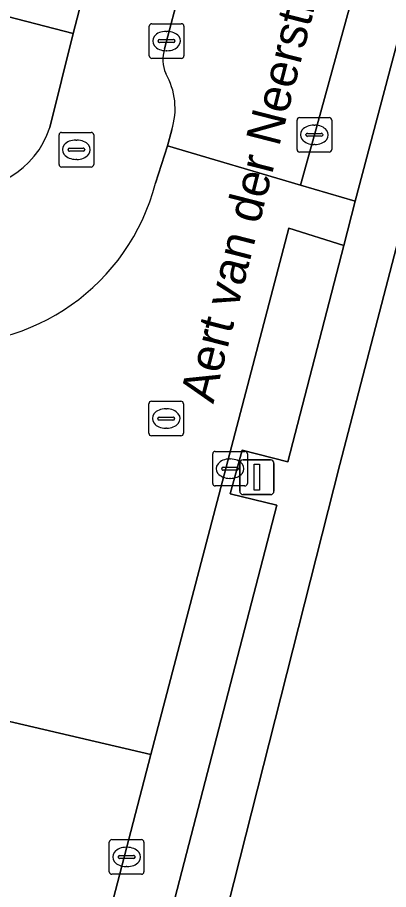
# Model space of a CAD drawing. Extents: x 163683 to 164494, y 382709 to 383872.
# Drawn here: x 164180.78 to 164191.5, y 383122.29 to 383147.46 of the extents above; entities that cross this region are included whole.
import ezdxf

# ---------------------------------------------------------------- set-up
doc = ezdxf.new("R2010")
doc.units = 0
for name, color, linetype in [('IMGEO_Brandkraan', 7, 'Continuous'), ('IMGEO_Erf', 7, 'Continuous'), ('IMGEO_Kolk', 7, 'Continuous'), ('IMGEO_Lichtmast', 7, 'Continuous'), ('IMGEO_Openbare_ruimte_label', 7, 'Continuous'), ('IMGEO_Pand', 7, 'Continuous'), ('IMGEO_Parkeervlak_open', 7, 'Continuous'), ('IMGEO_Rijbaan_lokaal_open', 7, 'Continuous'), ('IMGEO_Rioolput', 7, 'Continuous'), ('IMGEO_Voetpad_open', 7, 'Continuous')]:
    doc.layers.add(name, color=color, linetype=linetype)

msp = doc.modelspace()

# ---------------------------------------------------------------- linework, layer by layer
at = {"layer": 'IMGEO_Brandkraan'}
for p, q in [((164181.984, 383143.218), (164181.984, 383144.07)), ((164182.059, 383144.144), (164182.911, 383144.144)), ((164182.985, 383144.07), (164182.985, 383143.218)), ((164182.472, 383143.924), (164182.497, 383143.924)), ((164182.243, 383143.638), (164182.243, 383143.65)), ((164182.681, 383143.601), (164182.283, 383143.601)), ((164182.286, 383143.687), (164182.684, 383143.687)), ((164182.727, 383143.65), (164182.727, 383143.638)), ((164182.495, 383143.364), (164182.47, 383143.364)), ((164182.911, 383143.144), (164182.059, 383143.144))]:
    msp.add_line(p, q, dxfattribs=at)
for points in [[(164181.984, 383143.218), (164181.984, 383144.07)], [(164182.059, 383144.144), (164182.911, 383144.144)], [(164182.985, 383144.07), (164182.985, 383143.218)], [(164182.911, 383143.144), (164182.059, 383143.144)]]:
    msp.add_lwpolyline(points, dxfattribs=at)
for centre, radius, start, end in [((164182.061, 383144.068), 0.0765, 91.552, 178.448), ((164182.061, 383144.068), 0.0765, 91.552, 178.448), ((164182.909, 383144.068), 0.0765, 1.552, 88.448), ((164182.909, 383144.068), 0.0765, 1.552, 88.448), ((164182.283, 383143.647), 0.0403, 85.8775, 175.7526), ((164182.28, 383143.637), 0.0366, 178.938, 274.7102), ((164182.684, 383143.644), 0.043, 264.8664, 352.4533), ((164182.688, 383143.649), 0.0386, 1.7309, 96.639), ((164182.061, 383143.22), 0.0765, 181.552, 268.448), ((164182.061, 383143.22), 0.0765, 181.552, 268.448), ((164182.909, 383143.22), 0.0765, 271.552, 358.448), ((164182.909, 383143.22), 0.0765, 271.552, 358.448)]:
    msp.add_arc(centre, radius, start, end, dxfattribs=at)
for centre, major_axis, ratio, start_param, end_param in [((164182.471, 383143.644), (-0.387, 0.002), 0.722429, 4.712389, 7.853982), ((164182.496, 383143.644), (-0.39, 0.002), 0.717154, 1.570796, 4.712389)]:
    msp.add_ellipse(centre, major_axis=major_axis, ratio=ratio, start_param=start_param, end_param=end_param, dxfattribs=at)
at = {"layer": 'IMGEO_Erf'}
for points in [[(164181.718, 383144.288), (164182.395, 383147.001), (164175.872, 383148.696), (164176.511, 383151.151), (164171.876, 383152.355), (164172.911, 383156.337), (164174.58, 383155.903), (164175.305, 383158.691), (164174.256, 383158.963), (164174.916, 383161.499), (164174.956, 383161.653), (164175.727, 383164.619), (164176.798, 383164.341), (164177.507, 383167.068), (164178.03, 383169.079), (164177.044, 383169.336), (164177.995, 383172.992)], [(164235.416, 383087.174), (164249.772, 383143.475), (164225.172, 383149.691), (164224.38, 383146.62), (164220.869, 383147.526), (164218.278, 383138.676), (164221.781, 383137.775), (164221.055, 383134.95), (164220.387, 383132.353), (164217.268, 383133.155), (164217.081, 383132.425), (164215.494, 383132.833), (164216.241, 383135.98), (164212.881, 383136.834), (164213.61, 383139.702), (164214.266, 383142.284), (164217.626, 383141.431), (164219.349, 383147.981), (164215.956, 383148.856), (164216.694, 383151.712), (164199.271, 383156.404), (164196.004, 383157.255), (164190.094, 383134.558), (164181.769, 383101.734)]]:
    msp.add_lwpolyline(points, dxfattribs=at)
msp.add_arc((164179.316, 383145.046), 2.518, 257.4677, 342.4732, dxfattribs=at)
at = {"layer": 'IMGEO_Kolk'}
for p, q in [((164184.663, 383147.281), (164185.515, 383147.281)), ((164184.588, 383146.355), (164184.588, 383147.207)), ((164185.076, 383147.061), (164185.101, 383147.061)), ((164185.589, 383147.207), (164185.589, 383146.355)), ((164184.847, 383146.775), (164184.847, 383146.787)), ((164185.285, 383146.738), (164184.887, 383146.738)), ((164184.89, 383146.824), (164185.288, 383146.824)), ((164185.331, 383146.787), (164185.331, 383146.775)), ((164185.099, 383146.501), (164185.074, 383146.501)), ((164185.515, 383146.281), (164184.663, 383146.281)), ((164188.856, 383143.648), (164188.856, 383144.5)), ((164188.931, 383144.574), (164189.783, 383144.574)), ((164189.857, 383144.5), (164189.857, 383143.648)), ((164189.344, 383144.354), (164189.369, 383144.354)), ((164189.115, 383144.068), (164189.115, 383144.08)), ((164189.553, 383144.031), (164189.155, 383144.031)), ((164189.158, 383144.117), (164189.556, 383144.117)), ((164189.599, 383144.08), (164189.599, 383144.068)), ((164189.367, 383143.794), (164189.342, 383143.794)), ((164189.783, 383143.574), (164188.931, 383143.574)), ((164186.497, 383134.937), (164187.349, 383134.937)), ((164186.422, 383134.011), (164186.422, 383134.863)), ((164186.91, 383134.717), (164186.935, 383134.717)), ((164187.423, 383134.863), (164187.423, 383134.011)), ((164186.681, 383134.431), (164186.681, 383134.443)), ((164187.119, 383134.394), (164186.721, 383134.394)), ((164186.724, 383134.48), (164187.122, 383134.48)), ((164187.165, 383134.443), (164187.165, 383134.431)), ((164186.933, 383134.157), (164186.908, 383134.157)), ((164187.349, 383133.937), (164186.497, 383133.937)), ((164183.435, 383122.803), (164183.435, 383123.655)), ((164183.51, 383123.729), (164184.362, 383123.729)), ((164184.436, 383123.655), (164184.436, 383122.803)), ((164183.923, 383123.509), (164183.948, 383123.509)), ((164183.694, 383123.223), (164183.694, 383123.235)), ((164184.132, 383123.186), (164183.734, 383123.186)), ((164183.737, 383123.272), (164184.135, 383123.272)), ((164184.178, 383123.235), (164184.178, 383123.223)), ((164183.946, 383122.949), (164183.921, 383122.949)), ((164184.362, 383122.729), (164183.51, 383122.729))]:
    msp.add_line(p, q, dxfattribs=at)
for points in [[(164184.663, 383147.281), (164185.515, 383147.281)], [(164184.588, 383146.355), (164184.588, 383147.207)], [(164185.589, 383147.207), (164185.589, 383146.355)], [(164185.515, 383146.281), (164184.663, 383146.281)], [(164188.856, 383143.648), (164188.856, 383144.5)], [(164188.931, 383144.574), (164189.783, 383144.574)], [(164189.857, 383144.5), (164189.857, 383143.648)], [(164189.783, 383143.574), (164188.931, 383143.574)], [(164186.497, 383134.937), (164187.349, 383134.937)], [(164186.422, 383134.011), (164186.422, 383134.863)], [(164187.423, 383134.863), (164187.423, 383134.011)], [(164187.349, 383133.937), (164186.497, 383133.937)], [(164183.435, 383122.803), (164183.435, 383123.655)], [(164183.51, 383123.729), (164184.362, 383123.729)], [(164184.436, 383123.655), (164184.436, 383122.803)], [(164184.362, 383122.729), (164183.51, 383122.729)]]:
    msp.add_lwpolyline(points, dxfattribs=at)
for centre, radius, start, end in [((164184.665, 383147.205), 0.0765, 91.552, 178.448), ((164184.665, 383147.205), 0.0765, 91.552, 178.448), ((164185.513, 383147.205), 0.0765, 1.552, 88.448), ((164185.513, 383147.205), 0.0765, 1.552, 88.448), ((164184.887, 383146.784), 0.0403, 85.8775, 175.7526), ((164184.884, 383146.774), 0.0366, 178.938, 274.7102), ((164185.288, 383146.781), 0.043, 264.8664, 352.4533), ((164185.292, 383146.786), 0.0386, 1.7309, 96.639), ((164184.665, 383146.357), 0.0765, 181.552, 268.448), ((164184.665, 383146.357), 0.0765, 181.552, 268.448), ((164185.513, 383146.357), 0.0765, 271.552, 358.448), ((164185.513, 383146.357), 0.0765, 271.552, 358.448), ((164188.933, 383144.498), 0.0765, 91.552, 178.448), ((164188.933, 383144.498), 0.0765, 91.552, 178.448), ((164189.781, 383144.498), 0.0765, 1.552, 88.448), ((164189.781, 383144.498), 0.0765, 1.552, 88.448), ((164189.155, 383144.077), 0.0403, 85.8775, 175.7526), ((164189.152, 383144.067), 0.0366, 178.938, 274.7102), ((164189.556, 383144.074), 0.043, 264.8664, 352.4533), ((164189.56, 383144.079), 0.0386, 1.7309, 96.639), ((164188.933, 383143.65), 0.0765, 181.552, 268.448), ((164188.933, 383143.65), 0.0765, 181.552, 268.448), ((164189.781, 383143.65), 0.0765, 271.552, 358.448), ((164189.781, 383143.65), 0.0765, 271.552, 358.448), ((164186.499, 383134.861), 0.0765, 91.552, 178.448), ((164186.499, 383134.861), 0.0765, 91.552, 178.448), ((164187.347, 383134.861), 0.0765, 1.552, 88.448), ((164187.347, 383134.861), 0.0765, 1.552, 88.448), ((164186.721, 383134.44), 0.0403, 85.8775, 175.7526), ((164186.718, 383134.43), 0.0366, 178.938, 274.7102), ((164187.122, 383134.437), 0.043, 264.8664, 352.4533), ((164187.126, 383134.442), 0.0386, 1.7309, 96.639), ((164186.499, 383134.013), 0.0765, 181.552, 268.448), ((164186.499, 383134.013), 0.0765, 181.552, 268.448), ((164187.347, 383134.013), 0.0765, 271.552, 358.448), ((164187.347, 383134.013), 0.0765, 271.552, 358.448), ((164183.512, 383123.653), 0.0765, 91.552, 178.448), ((164183.512, 383123.653), 0.0765, 91.552, 178.448), ((164184.36, 383123.653), 0.0765, 1.552, 88.448), ((164184.36, 383123.653), 0.0765, 1.552, 88.448), ((164183.734, 383123.232), 0.0403, 85.8775, 175.7526), ((164183.731, 383123.222), 0.0366, 178.938, 274.7102), ((164184.135, 383123.229), 0.043, 264.8664, 352.4533), ((164184.139, 383123.234), 0.0386, 1.7309, 96.639), ((164183.512, 383122.805), 0.0765, 181.552, 268.448), ((164183.512, 383122.805), 0.0765, 181.552, 268.448), ((164184.36, 383122.805), 0.0765, 271.552, 358.448), ((164184.36, 383122.805), 0.0765, 271.552, 358.448)]:
    msp.add_arc(centre, radius, start, end, dxfattribs=at)
for centre, major_axis, ratio, start_param, end_param in [((164185.075, 383146.781), (-0.387, 0.002), 0.722429, 4.712389, 7.853982), ((164185.1, 383146.781), (-0.39, 0.002), 0.717154, 1.570796, 4.712389), ((164189.343, 383144.074), (-0.387, 0.002), 0.722429, 4.712389, 7.853982), ((164189.368, 383144.074), (-0.39, 0.002), 0.717154, 1.570796, 4.712389), ((164186.909, 383134.437), (-0.387, 0.002), 0.722429, 4.712389, 7.853982), ((164186.934, 383134.437), (-0.39, 0.002), 0.717154, 1.570796, 4.712389), ((164183.922, 383123.229), (-0.387, 0.002), 0.722429, 4.712389, 7.853982), ((164183.947, 383123.229), (-0.39, 0.002), 0.717154, 1.570796, 4.712389)]:
    msp.add_ellipse(centre, major_axis=major_axis, ratio=ratio, start_param=start_param, end_param=end_param, dxfattribs=at)
at = {"layer": 'IMGEO_Lichtmast'}
for p, q in [((164187.3, 383134.688), (164188.09, 383134.688)), ((164188.09, 383134.688), (164187.3, 383134.688)), ((164187.2, 383133.788), (164187.2, 383134.588)), ((164187.2, 383134.588), (164187.2, 383133.788)), ((164188.19, 383134.588), (164188.19, 383133.788)), ((164188.19, 383133.788), (164188.19, 383134.588)), ((164188.09, 383133.688), (164187.3, 383133.688)), ((164187.3, 383133.688), (164188.09, 383133.688))]:
    msp.add_line(p, q, dxfattribs=at)
msp.add_lwpolyline([(164187.62, 383134.563), (164187.77, 383134.563), (164187.77, 383133.813), (164187.62, 383133.813), (164187.62, 383134.563)], dxfattribs=at)
for centre, start, end in [((164187.3, 383134.588), 90, 180), ((164187.3, 383134.588), 90, 180), ((164188.09, 383134.588), 0, 90), ((164188.09, 383134.588), 360, 90), ((164187.3, 383133.788), 180, 270), ((164187.3, 383133.788), 180, 270), ((164188.09, 383133.788), 270, 0), ((164188.09, 383133.788), 270, 0)]:
    msp.add_arc(centre, 0.1, start, end, dxfattribs=at)
at = {"layer": 'IMGEO_Pand'}
msp.add_lwpolyline([(164184.067, 383153.438), (164174.58, 383155.903), (164172.911, 383156.337), (164171.876, 383152.355), (164176.511, 383151.151), (164175.872, 383148.696), (164182.395, 383147.001)], close=True, dxfattribs=at)
at = {"layer": 'IMGEO_Parkeervlak_open'}
for points in [[(164193.665, 383159.724), (164189.357, 383144.074), (164188.959, 383142.625), (164190.534, 383142.159), (164191.595, 383146.154), (164194.849, 383158.324)], [(164181.165, 383106.231), (164182.993, 383113.017), (164188.276, 383133.387), (164186.93, 383133.713), (164187.272, 383134.967), (164188.588, 383134.63), (164190.203, 383140.877), (164188.616, 383141.38), (164184.638, 383126.187), (164178.941, 383104.293)]]:
    msp.add_lwpolyline(points, dxfattribs=at)
at = {"layer": 'IMGEO_Rijbaan_lokaal_open'}
for points in [[(164195.962, 383188.713), (164195.791, 383188.078), (164194.358, 383182.464), (164189.313, 383162.614), (164185.499, 383148.358), (164185.032, 383146.554)], [(164185.239, 383144.22), (164185.117, 383143.761), (164188.959, 383142.625), (164189.357, 383144.074), (164193.665, 383159.724), (164194.577, 383163.198), (164195.035, 383165.03), (164200.503, 383185.752)], [(164188.616, 383141.38), (164190.203, 383140.877), (164190.534, 383142.159), (164188.959, 383142.625), (164185.117, 383143.761), (164184.767, 383142.677)], [(164180.219, 383128.415), (164179.925, 383127.281), (164184.638, 383126.187), (164188.616, 383141.38)], [(164184.638, 383126.187), (164179.925, 383127.281), (164173.185, 383101.113)], [(164178.941, 383104.293), (164184.638, 383126.187)]]:
    msp.add_lwpolyline(points, dxfattribs=at)
for centre, radius, start, end in [((164185.967, 383146.241), 0.986, 161.498, 203.6704), ((164183.313, 383144.834), 2.022, 342.3085, 29.9848), ((164178.777, 383144.224), 6.187, 264.7716, 345.5193)]:
    msp.add_arc(centre, radius, start, end, dxfattribs=at)
at = {"layer": 'IMGEO_Rioolput'}
for p, q in [((164184.578, 383135.458), (164184.578, 383136.31)), ((164184.653, 383136.384), (164185.505, 383136.384)), ((164185.066, 383136.164), (164185.091, 383136.164)), ((164185.579, 383136.31), (164185.579, 383135.458)), ((164184.837, 383135.878), (164184.837, 383135.89)), ((164184.88, 383135.927), (164185.278, 383135.927)), ((164185.321, 383135.89), (164185.321, 383135.878)), ((164185.275, 383135.841), (164184.877, 383135.841)), ((164185.089, 383135.604), (164185.064, 383135.604)), ((164185.505, 383135.384), (164184.653, 383135.384))]:
    msp.add_line(p, q, dxfattribs=at)
for points in [[(164184.578, 383135.458), (164184.578, 383136.31)], [(164184.653, 383136.384), (164185.505, 383136.384)], [(164185.579, 383136.31), (164185.579, 383135.458)], [(164185.505, 383135.384), (164184.653, 383135.384)]]:
    msp.add_lwpolyline(points, dxfattribs=at)
for centre, radius, start, end in [((164184.655, 383136.308), 0.0765, 91.552, 178.448), ((164184.655, 383136.308), 0.0765, 91.552, 178.448), ((164185.503, 383136.308), 0.0765, 1.552, 88.448), ((164185.503, 383136.308), 0.0765, 1.552, 88.448), ((164184.877, 383135.887), 0.0403, 85.8775, 175.7526), ((164185.282, 383135.889), 0.0386, 1.7309, 96.639), ((164184.874, 383135.877), 0.0366, 178.938, 274.7102), ((164185.278, 383135.884), 0.043, 264.8664, 352.4533), ((164184.655, 383135.46), 0.0765, 181.552, 268.448), ((164184.655, 383135.46), 0.0765, 181.552, 268.448), ((164185.503, 383135.46), 0.0765, 271.552, 358.448), ((164185.503, 383135.46), 0.0765, 271.552, 358.448)]:
    msp.add_arc(centre, radius, start, end, dxfattribs=at)
for centre, major_axis, ratio, start_param, end_param in [((164185.065, 383135.884), (-0.387, 0.002), 0.722429, 4.712389, 7.853982), ((164185.09, 383135.884), (-0.39, 0.002), 0.717154, 1.570796, 4.712389)]:
    msp.add_ellipse(centre, major_axis=major_axis, ratio=ratio, start_param=start_param, end_param=end_param, dxfattribs=at)
at = {"layer": 'IMGEO_Voetpad_open'}
for points in [[(164196.623, 383196.306), (164194.537, 383193.772), (164193.301, 383189.011), (164192.826, 383187.181), (164184.107, 383153.593), (164184.067, 383153.438), (164182.395, 383147.001), (164181.718, 383144.288)], [(164185.032, 383146.554), (164185.499, 383148.358), (164189.313, 383162.614), (164194.358, 383182.464)], [(164190.094, 383134.558), (164196.004, 383157.255), (164196.458, 383158.996), (164202.633, 383182.709)], [(164194.463, 383158.425), (164194.849, 383158.324), (164191.595, 383146.154), (164190.534, 383142.159), (164190.203, 383140.877), (164188.588, 383134.63), (164187.272, 383134.967), (164186.93, 383133.713), (164188.276, 383133.387), (164182.993, 383113.017), (164181.165, 383106.231)], [(164184.767, 383142.677), (164185.117, 383143.761), (164185.239, 383144.22)], [(164181.769, 383101.734), (164190.094, 383134.558)]]:
    msp.add_lwpolyline(points, dxfattribs=at)
for centre, radius, start, end in [((164185.967, 383146.241), 0.986, 161.498, 203.6704), ((164183.313, 383144.834), 2.022, 342.3085, 29.9848), ((164179.316, 383145.046), 2.518, 257.4677, 342.4732), ((164178.777, 383144.224), 6.187, 264.7716, 345.5193)]:
    msp.add_arc(centre, radius, start, end, dxfattribs=at)

# ---------------------------------------------------------------- texts
at = {"layer": 'IMGEO_Openbare_ruimte_label'}
msp.add_text('Aert van der Neerstraat', height=1, rotation=75.6442, dxfattribs=at).set_placement((164186.438, 383136.292))

doc.saveas('drawing.dxf')
